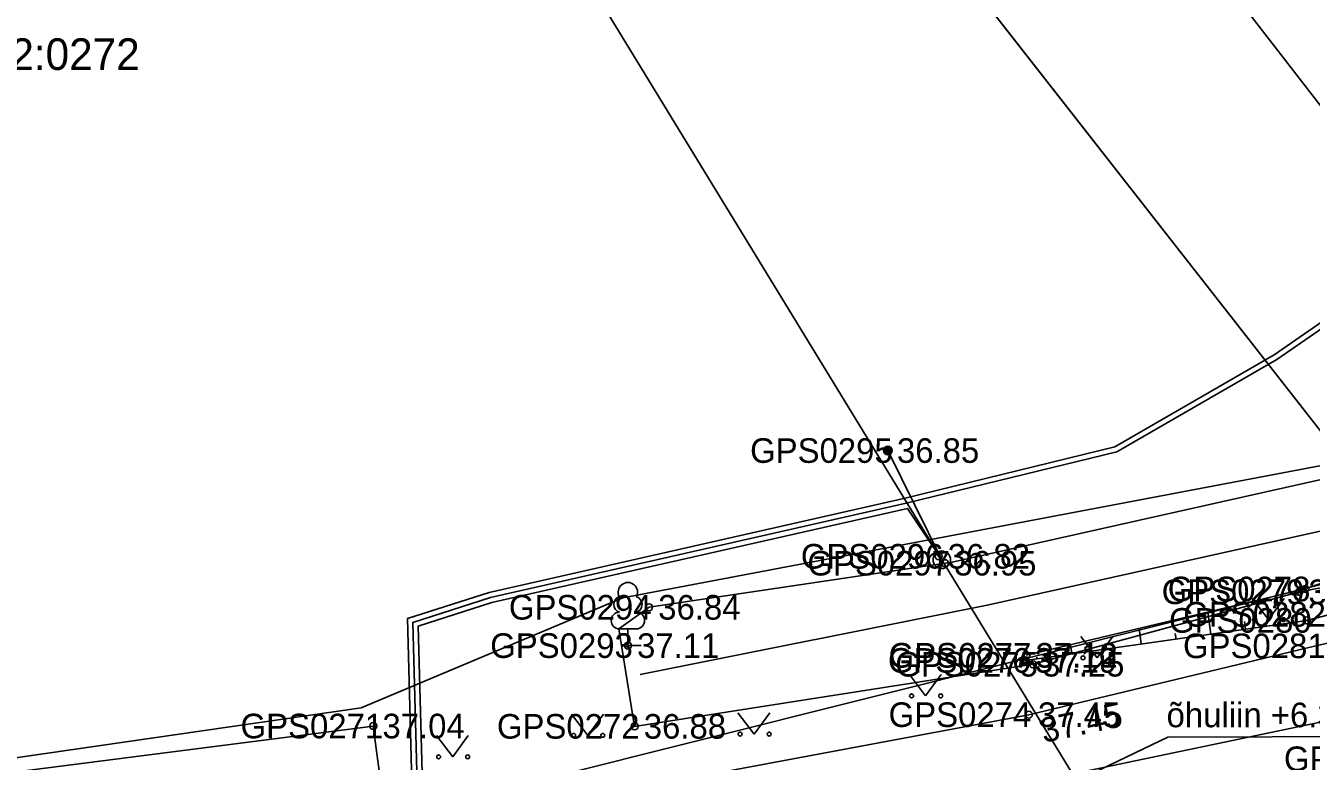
# Model space of a CAD drawing. Extents: x 626224 to 628280, y 6467750 to 6471135.
# Drawn here: x 627646.98 to 627683.58, y 6468627 to 6468647.94 of the extents above; entities that cross this region are included whole.
import ezdxf

# ---------------------------------------------------------------- set-up
doc = ezdxf.new("R2010")
doc.units = 0
for name, color, linetype in [('HALJASTUS', 7, 'Continuous'), ('KORGUS-EH2000', 7, 'Continuous'), ('KPKAABEL', 7, 'Continuous'), ('MOOTKORG-EH2000', 7, 'Continuous'), ('MOOTMPUNKT', 7, 'Continuous'), ('MOOTNR', 7, 'Continuous'), ('MOOTPIIR', 7, 'Continuous'), ('MPKAABEL', 7, 'Continuous'), ('MPOHULIIN', 7, 'Continuous'), ('PIIR', 7, 'Continuous'), ('POST', 7, 'Continuous'), ('PUU', 7, 'Continuous'), ('RELJEEF', 7, 'Continuous'), ('TEE', 7, 'Continuous'), ('Tee Liiklusala', 7, 'Continuous'), ('Tee Muu tee Püsikate', 7, 'Continuous')]:
    doc.layers.add(name, color=color, linetype=linetype)

msp = doc.modelspace()

# ---------------------------------------------------------------- linework, layer by layer
at = {"layer": 'HALJASTUS'}
for p, q in [((627681.896, 6468631.637), (627682.36, 6468631.031)), ((627682.36, 6468631.031), (627682.805, 6468631.637)), ((627677.016, 6468630.552), (627677.479, 6468629.945)), ((627677.479, 6468629.945), (627677.925, 6468630.552)), ((627672.135, 6468629.466), (627672.598, 6468628.86)), ((627672.598, 6468628.86), (627673.044, 6468629.466)), ((627662.515, 6468628.343), (627662.979, 6468627.737)), ((627662.979, 6468627.737), (627663.424, 6468628.343)), ((627667.254, 6468628.381), (627667.717, 6468627.774)), ((627667.717, 6468627.774), (627668.163, 6468628.381)), ((627658.671, 6468627.731), (627659.135, 6468627.125)), ((627659.135, 6468627.125), (627659.58, 6468627.731))]:
    msp.add_line(p, q, dxfattribs=at)
for points in [[(627664.314, 6468627.994), (627663.863, 6468630.771), (627664.725, 6468631.383), (627673.353, 6468632.664), (627686.946, 6468635.712)], [(627664.47, 6468629.471), (627674.392, 6468631.453), (627687.331, 6468634.332)], [(627689.052, 6468632.927), (627683.236, 6468631.825), (627675.654, 6468629.762), (627664.314, 6468627.994)], [(627636.336, 6468625.375), (627656.875, 6468628.003), (627657.149, 6468625.947), (627654.322, 6468625.361), (627643.674, 6468624.206), (627636.948, 6468623.11), (627636.336, 6468625.375)]]:
    msp.add_lwpolyline(points, dxfattribs=at)
for centre in [(627681.959, 6468631.031), (627682.787, 6468631.031), (627677.078, 6468629.945), (627677.907, 6468629.945), (627672.197, 6468628.86), (627673.026, 6468628.86), (627667.316, 6468627.774), (627668.145, 6468627.774), (627662.578, 6468627.737), (627663.407, 6468627.737), (627658.734, 6468627.125), (627659.562, 6468627.125)]:
    msp.add_circle(centre, 0.055, dxfattribs=at)
at = {"layer": 'KORGUS-EH2000'}
msp.add_circle((627675.534, 6468628.326), 0.1, dxfattribs=at)
at = {"layer": 'KPKAABEL'}
msp.add_lwpolyline([(627685.782, 6468640.643), (627682.599, 6468638.441), (627678.043, 6468635.809), (627672.046, 6468634.344), (627660.214, 6468631.662), (627657.997, 6468630.954), (627658.117, 6468626.708), (627657.689, 6468626.13), (627652.495, 6468625.008), (627640.455, 6468623.259), (627628.481, 6468622.246), (627623.048, 6468622.007), (627612.632, 6468622.516), (627609.034, 6468622.858), (627605.474, 6468623.034), (627601.854, 6468622.409), (627599.956, 6468622.4), (627599.775, 6468623.347)], dxfattribs=at)
at = {"layer": 'MOOTMPUNKT'}
for centre in [(627671.521, 6468635.845), (627672.966, 6468632.835), (627673.15, 6468632.638), (627683.236, 6468631.825), (627683.41, 6468631.904), (627664.725, 6468631.383), (627683.446, 6468631.01), (627664.123, 6468630.292), (627675.465, 6468630.016), (627675.445, 6468629.871), (627675.654, 6468629.762), (627675.534, 6468628.326), (627656.875, 6468628.003), (627664.314, 6468627.994)]:
    msp.add_circle(centre, 0.1, dxfattribs=at)
at = {"layer": 'MOOTPIIR'}
msp.add_lwpolyline([(627725.17, 6468593.561), (627699.891, 6468628.007), (627691.556, 6468636.216), (627689.682, 6468635.294), (627688.429, 6468634.933), (627687.779, 6468636.161), (627663.981, 6468631.653), (627656.533, 6468628.521), (627633.238, 6468625.152)], dxfattribs=at)
at = {"layer": 'MPKAABEL'}
for points in [[(627685.699, 6468640.768), (627682.519, 6468638.568), (627677.987, 6468635.95), (627672.012, 6468634.49), (627660.175, 6468631.807), (627657.844, 6468631.063), (627657.966, 6468626.756), (627657.602, 6468626.265), (627652.468, 6468625.156), (627640.438, 6468623.408), (627628.471, 6468622.396), (627623.048, 6468622.157), (627612.643, 6468622.666), (627609.045, 6468623.008), (627605.465, 6468623.185), (627601.841, 6468622.559), (627601.344, 6468627.176), (627599.992, 6468627.142), (627599.551, 6468626.364)], [(627599.73, 6468626.375), (627600.081, 6468626.994), (627601.209, 6468627.023), (627601.759, 6468622.259), (627605.483, 6468622.883), (627609.023, 6468622.708), (627612.621, 6468622.366), (627623.048, 6468621.857), (627628.491, 6468622.096), (627640.472, 6468623.11), (627652.522, 6468624.86), (627657.776, 6468625.995), (627658.268, 6468626.66), (627658.15, 6468630.845), (627660.253, 6468631.517), (627672.08, 6468634.198), (627673.058, 6468632.736)], [(627685.401, 6468627.702), (627679.495, 6468627.683), (627676.897, 6468626.445)]]:
    msp.add_lwpolyline(points, dxfattribs=at)
at = {"layer": 'MPOHULIIN'}
for points in [[(627672.71, 6468633.307), (627650.309, 6468669.981)], [(627679.915, 6468621.5), (627673.058, 6468632.736), (627672.71, 6468633.307)]]:
    msp.add_lwpolyline(points, dxfattribs=at)
at = {"layer": 'PIIR'}
for points in [[(627746.91, 6468541.23), (627688.18, 6468626.77), (627684.35, 6468632.16), (627686.69, 6468632.75), (627663.66, 6468662.2), (627667.34, 6468664.86), (627649.05, 6468692.73), (627646.31, 6468691.19), (627629.12, 6468721.76), (627618.92, 6468715.04), (627606.91, 6468724.16), (627579.16, 6468687.58), (627549.96, 6468707.41), (627588.77, 6468756.22), (627618.05, 6468733.86), (627619.84, 6468735.06), (627604.18, 6468764.29), (627579.83, 6468812.09), (627559.2, 6468856.67), (627547.01, 6468886.57), (627533.67, 6468925.79), (627531.86, 6468935.62), (627512.37, 6469002.4)], [(627401.5, 6468603.97), (627489.68, 6468613.41), (627577.55, 6468622.81), (627581.38, 6468622.85), (627583, 6468623.57), (627584.27, 6468624.13), (627586.23, 6468625.97), (627588.94, 6468620.18), (627605.69, 6468621.95), (627623.24, 6468621.3), (627652.69, 6468624.22), (627684.35, 6468632.16), (627688.18, 6468626.77), (627643.52, 6468618.24), (627599.49, 6468616.8), (627555.29, 6468612.05), (627411.34, 6468595.13)]]:
    msp.add_lwpolyline(points, dxfattribs=at)
msp.add_lwpolyline([(627654.85, 6468663.52), (627663.66, 6468662.2), (627686.69, 6468632.75), (627684.35, 6468632.16), (627652.69, 6468624.22), (627623.24, 6468621.3), (627605.69, 6468621.95), (627588.94, 6468620.18), (627586.23, 6468625.97), (627596.31, 6468635.4), (627619.6, 6468659.76), (627624.98, 6468665.39), (627633.24, 6468674.95), (627637.73, 6468680.5), (627640.48, 6468683.65), (627644.86, 6468680.34)], close=True, dxfattribs=at)
at = {"layer": 'POST'}
msp.add_lwpolyline([(627671.521, 6468635.845), (627673.058, 6468632.736)], dxfattribs=at)
for centre, radius in [((627671.521, 6468635.845), 0.125), ((627671.521, 6468635.845), 0.105), ((627671.521, 6468635.845), 0.0851), ((627671.521, 6468635.845), 0.0651), ((627671.521, 6468635.845), 0.0451), ((627671.521, 6468635.845), 0.0251), ((627671.521, 6468635.845), 0.00511), ((627673.058, 6468632.736), 0.25)]:
    msp.add_circle(centre, radius, dxfattribs=at)
at = {"layer": 'PUU'}
for p, q in [((627664.363, 6468630.767), (627663.883, 6468630.767)), ((627664.123, 6468630.292), (627664.123, 6468630.767)), ((627664.503, 6468630.292), (627664.123, 6468630.292))]:
    msp.add_line(p, q, dxfattribs=at)
for centre, radius, start, end in [((627664.123, 6468631.812), 0.277, 332.5799, 207.4201), ((627663.953, 6468631.465), 0.233, 109.0217, 253.1415), ((627664.293, 6468631.465), 0.233, 286.8508, 70.9859), ((627663.885, 6468631.005), 0.238, 90.0016, 269.3953), ((627664.36, 6468631.005), 0.238, 270.6047, 89.9984)]:
    msp.add_arc(centre, radius, start, end, dxfattribs=at)
at = {"layer": 'RELJEEF'}
for p, q in [((627682.696, 6468630.903), (627682.581, 6468631.707)), ((627680.716, 6468630.621), (627680.627, 6468631.243)), ((627678.736, 6468630.34), (627678.673, 6468630.779)), ((627681.706, 6468630.762), (627681.675, 6468630.976)), ((627679.726, 6468630.48), (627679.703, 6468630.64)), ((627676.756, 6468630.058), (627676.719, 6468630.314)), ((627677.746, 6468630.199), (627677.731, 6468630.303)), ((627675.766, 6468629.917), (627675.759, 6468629.967))]:
    msp.add_line(p, q, dxfattribs=at)
for points in [[(627689.682, 6468635.294), (627690.235, 6468634.267), (627690.092, 6468633.472), (627689.259, 6468632.526), (627683.446, 6468631.01), (627675.445, 6468629.871)], [(627688.429, 6468634.933), (627688.985, 6468633.865), (627683.41, 6468631.904), (627675.465, 6468630.016)]]:
    msp.add_lwpolyline(points, dxfattribs=at)
at = {"layer": 'TEE'}
msp.add_lwpolyline([(627691.556, 6468636.216), (627691.411, 6468633.572), (627690.377, 6468632.362), (627688.302, 6468631.311), (627683.705, 6468630.285), (627675.534, 6468628.326), (627664.963, 6468626.349), (627655.323, 6468624.553), (627656.855, 6468621.064), (627660.849, 6468621.603), (627663.795, 6468622.181), (627671.677, 6468623.939), (627678.512, 6468625.342), (627686.437, 6468627.071), (627694.212, 6468628.779), (627696.498, 6468628.635), (627697.947, 6468628.287), (627705.762, 6468618.126), (627714.785, 6468606.184), (627724.497, 6468592.392)], dxfattribs=at)
at = {"layer": 'Tee Liiklusala'}
msp.add_lwpolyline([(627770.48, 6468525.39), (627740.557, 6468568.764), (627738.71, 6468571.44), (627735.13, 6468576.26), (627712.14, 6468607.18), (627694.794, 6468631.457), (627678.044, 6468653.167), (627666.826, 6468668.407), (627651.484, 6468693.118), (627649.736, 6468695.878), (627641.743, 6468708.498), (627640.999, 6468709.875), (627623.478, 6468742.312), (627616.983, 6468754.336), (627595.384, 6468797.487), (627592.828, 6468802.833), (627577.59, 6468834.7), (627567.06, 6468857.03), (627562.51, 6468869.71), (627561.06, 6468873.68), (627543.04, 6468921.76), (627539.249, 6468933.164), (627537.18, 6468939.44), (627530.65, 6468964.53)], dxfattribs=at)
at = {"layer": 'Tee Muu tee Püsikate'}
msp.add_lwpolyline([(627700.902, 6468634.138), (627694.794, 6468631.457), (627685.552, 6468628.47), (627661.394, 6468623.428), (627655.281, 6468622.513)], dxfattribs=at)

# ---------------------------------------------------------------- texts
at = {"layer": 'KORGUS-EH2000'}
msp.add_text(' 37.45', height=0.7, rotation=11.9253, dxfattribs=at).set_placement((627675.703, 6468627.467))
at = {"layer": 'MOOTKORG-EH2000'}
for s, p in [(' 36.85', (627671.521, 6468635.495)), (' 36.82', (627672.966, 6468632.485)), (' 36.95', (627673.15, 6468632.288)), (' 37.16', (627683.236, 6468631.475)), (' 36.84', (627664.725, 6468631.033)), (' 37.11', (627664.123, 6468629.942)), (' 37.19', (627675.445, 6468629.521)), (' 37.12', (627675.465, 6468629.666)), (' 37.25', (627675.654, 6468629.412)), (' 37.45', (627675.534, 6468627.976)), (' 37.04', (627656.875, 6468627.653)), (' 36.88', (627664.314, 6468627.644))]:
    msp.add_text(s, height=0.7, dxfattribs=at).set_placement(p)
at = {"layer": 'MOOTNR'}
for s, p in [('GPS0295 ', (627667.601, 6468635.495)), ('GPS0296 ', (627669.046, 6468632.485)), ('GPS0297 ', (627669.231, 6468632.288)), ('GPS0278 ', (627679.49, 6468631.554)), ('GPS0279 ', (627679.317, 6468631.475)), ('GPS0294 ', (627660.735, 6468631.033)), ('GPS0282 ', (627679.933, 6468630.833)), ('GPS0280 ', (627679.526, 6468630.66)), ('GPS0293 ', (627660.203, 6468629.942)), ('GPS0281 ', (627679.925, 6468629.935)), ('GPS0276 ', (627671.525, 6468629.521)), ('GPS0277 ', (627671.545, 6468629.666)), ('GPS0275 ', (627671.734, 6468629.412)), ('GPS0274 ', (627671.544, 6468627.976)), ('GPS0271 ', (627653.096, 6468627.653)), ('GPS0272 ', (627660.394, 6468627.644)), ('GPS0161 ', (627682.797, 6468626.721))]:
    msp.add_text(s, height=0.7, dxfattribs=at).set_placement(p)
at = {"layer": 'MPKAABEL'}
msp.add_text('õhuliin +6.30m', height=0.7, dxfattribs=at).set_placement((627679.457, 6468627.969))
at = {"layer": 'PIIR'}
msp.add_text('66601:002:0272', height=0.9, dxfattribs=at).set_placement((627641.524, 6468646.68))

doc.saveas('drawing.dxf')
